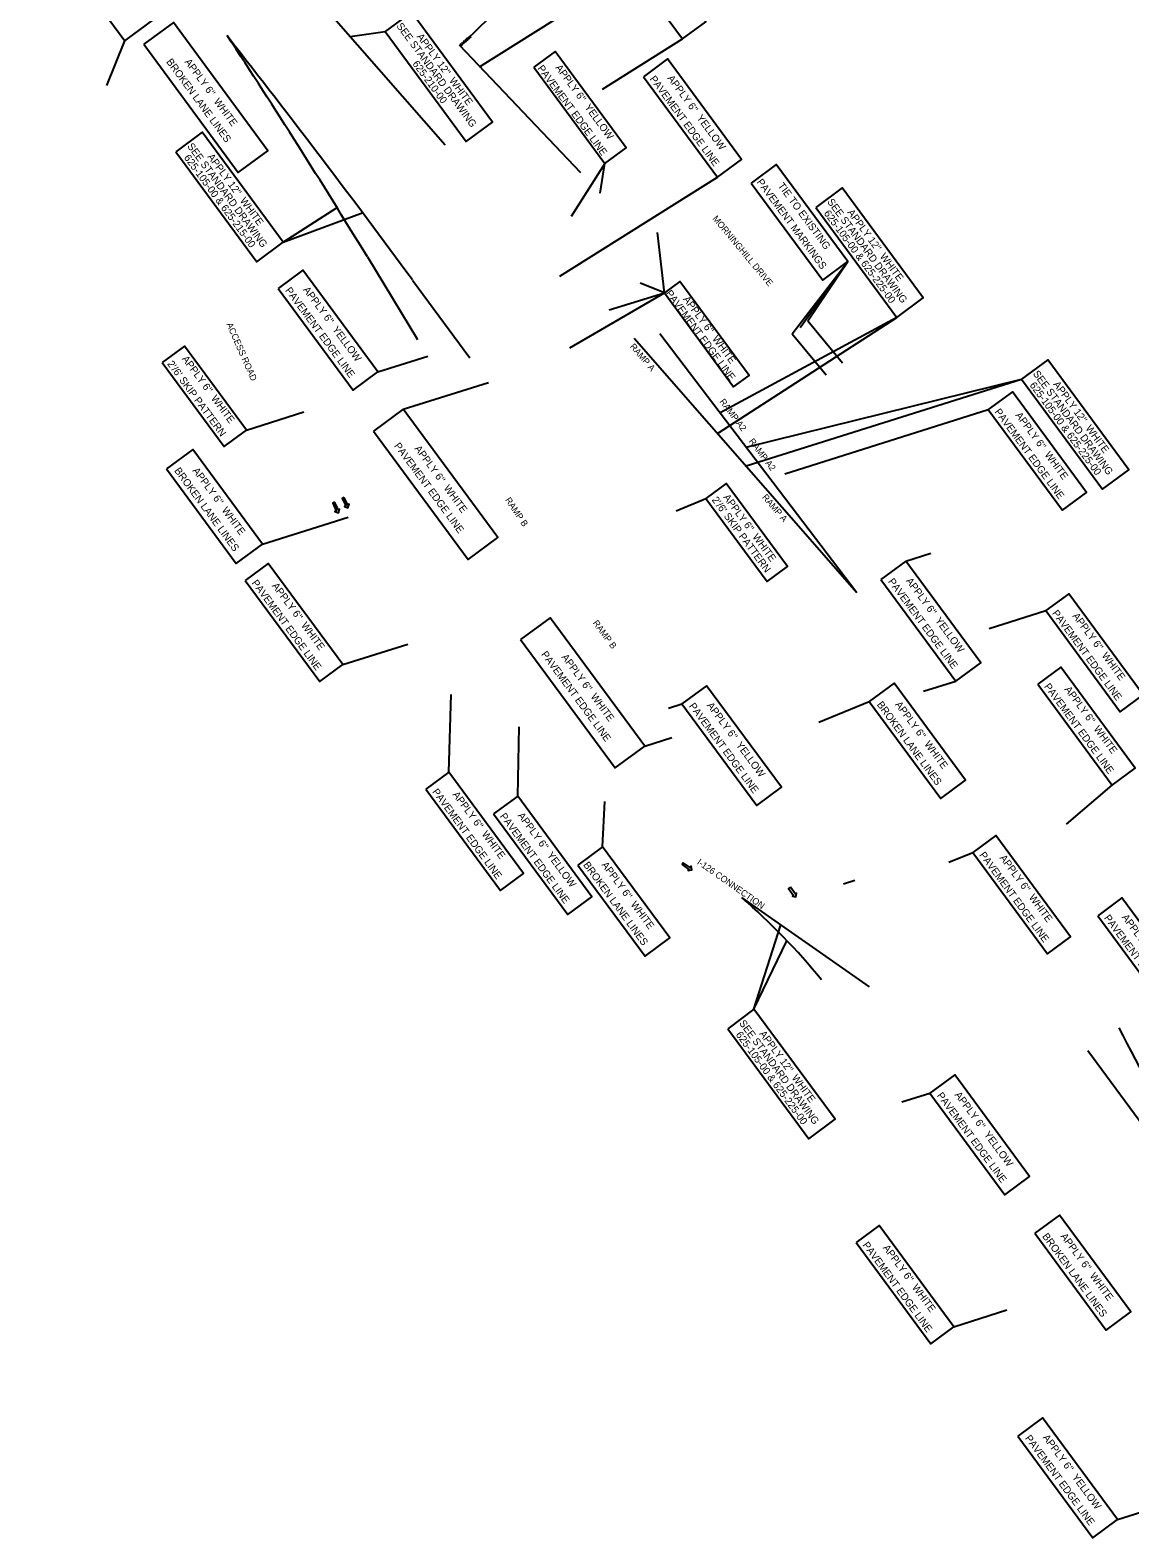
# Model space of a CAD drawing. Extents: x 1966013 to 1974896, y 789499 to 804826.
# Drawn here: x 1970033 to 1971229, y 795539 to 797178 of the extents above; entities that cross this region are included whole.
import ezdxf

# ---------------------------------------------------------------- set-up
doc = ezdxf.new("R2010")
doc.units = 0
for name, color, linetype in [('RD_EX_H2O_BlueLn', 7, 'Continuous'), ('RD_PD_Final_Cl', 7, 'Continuous'), ('RD_PD_Final_LnLine', 7, 'Continuous'), ('RD_PD_MedBWall', 7, 'Continuous')]:
    doc.layers.add(name, color=color, linetype=linetype)

msp = doc.modelspace()

# ---------------------------------------------------------------- linework, layer by layer
at = {"layer": 'RD_EX_H2O_BlueLn'}
for p, q in [((1970507, 797167), (1970581.9, 797240.7)), ((1970521.6, 797138.2), (1970648.7, 797217.9)), ((1970380.7, 797171.2), (1970418.8, 797176.4)), ((1970116.1, 797117.8), (1970135.6, 797166.3)), ((1970500.4, 797162.4), (1970501.6, 797163.3)), ((1970502.4, 797161.1), (1970500.4, 797162.4)), ((1970501.6, 797163.3), (1970502.4, 797161.1)), ((1970502.3, 797164), (1970503.5, 797165)), ((1970504.3, 797162.8), (1970502.3, 797164)), ((1970503.5, 797165), (1970504.3, 797162.8)), ((1970504.2, 797165.6), (1970505.3, 797166.6)), ((1970506.2, 797164.4), (1970504.2, 797165.6)), ((1970505.3, 797166.6), (1970506.2, 797164.4)), ((1970506.1, 797167.3), (1970507.3, 797168.3)), ((1970508.1, 797166.1), (1970506.1, 797167.3)), ((1970507.3, 797168.3), (1970508.1, 797166.1)), ((1970507.9, 797168.9), (1970509, 797169.9)), ((1970509.9, 797167.7), (1970507.9, 797168.9)), ((1970509, 797169.9), (1970509.9, 797167.7)), ((1970509.8, 797170.5), (1970510.9, 797171.5)), ((1970511.8, 797169.3), (1970509.8, 797170.5)), ((1970510.9, 797171.5), (1970511.8, 797169.3)), ((1970655.2, 797113.8), (1970742.3, 797168.4)), ((1970657.8, 797032.9), (1970621.2, 796975.5)), ((1970652.7, 797000.8), (1970657.8, 797032.9)), ((1970609.1, 796910.5), (1970780.4, 797018)), ((1970308, 796947.3), (1970366.6, 796985)), ((1970308, 796947.3), (1970395.1, 796979.6)), ((1970722.6, 796892.2), (1970715.2, 796957.9)), ((1970861.7, 796847.8), (1970922.3, 796926.5)), ((1970870.2, 796854.8), (1970922.3, 796926.5)), ((1970878.6, 796861.8), (1970922.3, 796926.5)), ((1970722.6, 796892.2), (1970696.3, 796902.9)), ((1970619.9, 796832.5), (1970722.6, 796892.2)), ((1970662.6, 796873.8), (1970722.6, 796892.2)), ((1970780.3, 796739.3), (1970975.5, 796865.7)), ((1970975.5, 796865.7), (1970783.2, 796762)), ((1970878.6, 796861.8), (1970916.3, 796816.2)), ((1970861.7, 796847.8), (1970898.6, 796803.1)), ((1970410.9, 796806.5), (1970465.4, 796823.6)), ((1970811.5, 796704.1), (1971111.1, 796798.4)), ((1970811.6, 796724.7), (1971111.1, 796798.4)), ((1970438.6, 796765.8), (1970531.2, 796795)), ((1970853.7, 796695.7), (1971075, 796765.4)), ((1970268, 796743.2), (1970330.6, 796762.9)), ((1970735.4, 796655.5), (1970767.9, 796668.8)), ((1970285.5, 796619.1), (1970378.8, 796648.5)), ((1970985.2, 796600.6), (1971012.5, 796609.2)), ((1971075.9, 796527.4), (1971137.4, 796546.8)), ((1970373, 796488.1), (1970443.7, 796510.4)), ((1971004.5, 796459.1), (1971039.7, 796470.2)), ((1970488.2, 796371.1), (1970490.7, 796455.5)), ((1970727.1, 796440.8), (1970741.7, 796445.3)), ((1970890.5, 796425.4), (1970945.5, 796447.9)), ((1970563.2, 796345), (1970564.8, 796420.5)), ((1970701.4, 796399.6), (1970730.9, 796408.9)), ((1971159.9, 796314.7), (1971209.8, 796357)), ((1970655.5, 796290.1), (1970657.7, 796339.4)), ((1971032.2, 796273.2), (1971058.3, 796283.8)), ((1970917.3, 796249.8), (1970929.8, 796253.7)), ((1970820.1, 796113.3), (1970849.3, 796205)), ((1970820.1, 796113.3), (1970855.9, 796187.7)), ((1970981.1, 796012.7), (1971011.5, 796022.2)), ((1971037.5, 795768.2), (1971095.3, 795786.4)), ((1971215.6, 795558.5), (1971320.9, 795591.6))]:
    msp.add_line(p, q, dxfattribs=at)
for points in [[(1970032.8, 797305.8), (1970135.6, 797166.3), (1970167.8, 797190), (1970065, 797329.5)], [(1970662.7, 797276.4), (1970742.3, 797168.4), (1970767.6, 797187.1), (1970688.1, 797295.1)], [(1970418.8, 797176.4), (1970506.9, 797056.8), (1970535.6, 797077.9), (1970447.4, 797197.5)], [(1970156.4, 797162.6), (1970259.2, 797023.1), (1970291.4, 797046.8), (1970188.6, 797186.4)], [(1970580.5, 797137.7), (1970657.8, 797032.9), (1970681, 797050), (1970603.8, 797154.8)], [(1970699.8, 797127.4), (1970780.4, 797018), (1970806.7, 797037.3), (1970726, 797146.7)], [(1970191.2, 797045.8), (1970279.4, 796926.2), (1970308, 796947.3), (1970219.8, 797066.9)], [(1970817, 797011.7), (1970895.1, 796906.3), (1970922.3, 796926.5), (1970844.2, 797031.9)], [(1970887.3, 796985.3), (1970975.5, 796865.7), (1971004.1, 796886.8), (1970916, 797006.4)], [(1970302.5, 796897.2), (1970384, 796786.6), (1970410.9, 796806.5), (1970329.4, 796917.1)], [(1970722.6, 796892.2), (1970797.9, 796790.1), (1970814.8, 796802.6), (1970739.6, 796904.7)], [(1970176.5, 796816.5), (1970243.7, 796725.3), (1970268, 796743.2), (1970200.8, 796834.4)], [(1971111.1, 796798.4), (1971199.3, 796678.8), (1971227.9, 796699.9), (1971139.7, 796819.5)], [(1971075, 796765.4), (1971155.6, 796656), (1971181.9, 796675.3), (1971101.2, 796784.7)], [(1970406.4, 796742.1), (1970509.3, 796602.5), (1970541.5, 796626.3), (1970438.6, 796765.8)], [(1970181.1, 796700.9), (1970256.9, 796598), (1970285.5, 796619.1), (1970209.7, 796721.9)], [(1970767.9, 796668.8), (1970834.4, 796578.5), (1970856.5, 796594.7), (1970789.9, 796685)], [(1970958.2, 796580.7), (1971039.7, 796470.2), (1971066.7, 796490), (1970985.2, 796600.6)], [(1970266.8, 796579.6), (1970347.9, 796469.6), (1970373, 796488.1), (1970291.8, 796598.1)], [(1971137.4, 796546.8), (1971218.5, 796436.7), (1971243.6, 796455.2), (1971162.5, 796565.2)], [(1970566.3, 796515.4), (1970669.2, 796375.9), (1970701.4, 796399.6), (1970598.5, 796539.1)], [(1971128.7, 796467), (1971209.8, 796357), (1971234.9, 796375.5), (1971153.8, 796485.5)], [(1970741.7, 796445.3), (1970823.2, 796334.8), (1970850.1, 796354.7), (1970768.6, 796465.2)], [(1970945.5, 796447.9), (1971023.2, 796342.6), (1971050.1, 796362.5), (1970972.5, 796467.8)], [(1970463.2, 796352.6), (1970544.3, 796242.5), (1970569.3, 796261), (1970488.2, 796371.1)], [(1970536.9, 796325.7), (1970617.6, 796216.3), (1970643.8, 796235.6), (1970563.2, 796345)], [(1970628.6, 796270.2), (1970701.7, 796171.1), (1970728.6, 796190.9), (1970655.5, 796290.1)], [(1971058.3, 796283.8), (1971139.4, 796173.8), (1971164.5, 796192.3), (1971083.3, 796302.3)], [(1971194.1, 796215.1), (1971274.7, 796105.7), (1971301, 796125), (1971220.3, 796234.4)], [(1970791.5, 796092.2), (1970879.7, 795972.6), (1970908.3, 795993.7), (1970820.1, 796113.3)], [(1971011.5, 796022.2), (1971093.1, 795911.6), (1971119.9, 795931.4), (1971038.4, 796042.1)], [(1970931.3, 795859.8), (1971012.4, 795749.7), (1971037.5, 795768.2), (1970956.3, 795878.2)], [(1971125.5, 795869.8), (1971203.1, 795764.5), (1971230, 795784.3), (1971152.4, 795889.6)], [(1971107.1, 795649.2), (1971188.6, 795538.6), (1971215.6, 795558.5), (1971134.1, 795669)]]:
    msp.add_lwpolyline(points, close=True, dxfattribs=at)
at = {"layer": 'RD_PD_Final_Cl'}
for points in [[(1970374.5, 796670), (1970372.3, 796668.9), (1970376.2, 796660.6), (1970374.7, 796659.9), (1970378.5, 796658.6), (1970379.9, 796662.4), (1970378.4, 796661.7)], [(1970364, 796664.7), (1970361.9, 796663.6), (1970365.8, 796655.3), (1970364.3, 796654.7), (1970368.1, 796653.3), (1970369.4, 796657.1), (1970368, 796656.4)], [(1970743.2, 796272.7), (1970741.9, 796270.7), (1970749.4, 796265.5), (1970748.4, 796264.2), (1970752.4, 796264.8), (1970751.7, 796268.8), (1970750.8, 796267.5)], [(1970859.7, 796246), (1970857.7, 796244.6), (1970863.2, 796237.2), (1970861.9, 796236.3), (1970865.8, 796235.7), (1970866.4, 796239.6), (1970865.1, 796238.6)]]:
    msp.add_lwpolyline(points, close=True, dxfattribs=at)
at = {"layer": 'RD_PD_Final_LnLine'}
for p, q in [((1970331.9, 797227), (1970484.2, 797053.2)), ((1970499.5, 797162.1), (1970631.3, 797023.2)), ((1970399.6, 796931.4), (1970454.2, 796841.8)), ((1970448.7, 796906.3), (1970511.1, 796821.7)), ((1970717.8, 796848.1), (1970931.8, 796566.4)), ((1970689.6, 796843), (1970931.8, 796566.4)), ((1970945.7, 796137.6), (1970806.8, 796234.9)), ((1971183.3, 796068.4), (1971259.3, 795965.3))]:
    msp.add_line(p, q, dxfattribs=at)
for centre, radius, start, end in [((1963181.8, 792526), 8456, 31.39766, 33.32963), ((1961201.8, 790089.5), 11488, 36.39766, 38.04902), ((1970326.5, 795682.5), 732, 39.2393, 48.9944), ((1972855.7, 796921.2), 1836, 206.8053, 216.4039)]:
    msp.add_arc(centre, radius, start, end, dxfattribs=at)

# ---------------------------------------------------------------- texts
at = {"layer": 'RD_EX_H2O_BlueLn'}
for s, height, rotation, p in [('SEE STANDARD DRAWING', 8, 306.3977, (1970430.8, 797182.4)), ("APPLY 12''  WHITE", 8, 306.3977, (1970452.8, 797170.8)), ('BROKEN LANE LINES', 8, 306.3977, (1970180.4, 797143.5)), ("APPLY 6''  WHITE", 8, 306.3977, (1970200.3, 797143.4)), ('625-210-00 ', 8, 306.3977, (1970448.2, 797141.3)), ('PAVEMENT EDGE LINE', 8, 306.3977, (1970584.2, 797136.4)), ("APPLY 6''  YELLOW", 8, 306.3977, (1970603.6, 797137.1)), ('PAVEMENT EDGE LINE', 8, 306.3977, (1970706.2, 797124.9)), ("APPLY 6''  YELLOW", 8, 306.3977, (1970725.5, 797125.6)), ('625-105-00 & 625-215-00', 8, 306.3977, (1970199.6, 797039.2)), ('SEE STANDARD DRAWING', 8, 306.3977, (1970203.2, 797051.7)), ("APPLY 12''  WHITE", 8, 306.3977, (1970225.2, 797040.2)), ('PAVEMENT MARKINGS', 8, 306.5163, (1970822.7, 797012.7)), ('TIE TO EXISTING', 8, 306.5163, (1970845.6, 797008.7)), ('SEE STANDARD DRAWING', 8, 306.3977, (1970899.3, 796991.3)), ('625-105-00 & 625-225-00', 8, 306.3977, (1970895.7, 796978.7)), ("APPLY 12''  WHITE", 8, 306.3977, (1970921.3, 796979.7)), ('PAVEMENT EDGE LINE', 8, 306.3977, (1970309.8, 796894.9)), ("APPLY 6''  YELLOW", 8, 306.3977, (1970329.2, 796895.6)), ('PAVEMENT EDGE LINE', 8, 306.3977, (1970723.6, 796891.8)), ("APPLY 6''  WHITE", 8, 306.3977, (1970742.5, 796885.3)), ("2'/6' SKIP PATTERN", 7.999, 306.3978, (1970181.4, 796815.1)), ("APPLY 6''  WHITE", 7.999, 306.3978, (1970197.4, 796820.5)), ('SEE STANDARD DRAWING', 8, 306.3977, (1971123.1, 796804.4)), ('625-105-00 & 625-225-00', 8, 306.3977, (1971119.5, 796791.8)), ("APPLY 12''  WHITE", 8, 306.3977, (1971145.1, 796792.8)), ('PAVEMENT EDGE LINE', 8, 306.3977, (1971081.4, 796762.9)), ("APPLY 6''  WHITE", 8, 306.3977, (1971104, 796759.2)), ('PAVEMENT EDGE LINE', 8, 306.3977, (1970428.3, 796725.9)), ("APPLY 6''  WHITE", 8, 306.3977, (1970450.4, 796722.9)), ('BROKEN LANE LINES', 8, 306.3977, (1970189.1, 796698.9)), ("APPLY 6''  WHITE", 8, 306.3977, (1970209, 796698.9)), ("2'/6' SKIP PATTERN", 7.999, 306.3978, (1970773.8, 796667.2)), ("APPLY 6''  WHITE", 7.999, 306.3978, (1970786.3, 796670)), ('PAVEMENT EDGE LINE', 8, 306.3977, (1970273.3, 796576.8)), ("APPLY 6''  WHITE", 8, 306.3977, (1970295.4, 796573.7)), ('PAVEMENT EDGE LINE', 8, 306.3977, (1970965.6, 796578.4)), ("APPLY 6''  YELLOW", 8, 306.3977, (1970984.9, 796579.1)), ('PAVEMENT EDGE LINE', 8, 306.3977, (1971144, 796543.9)), ("APPLY 6''  WHITE", 8, 306.3977, (1971166.1, 796540.9)), ('PAVEMENT EDGE LINE', 8, 306.3977, (1970588.2, 796499.2)), ("APPLY 6''  WHITE", 8, 306.3977, (1970610.3, 796496.2)), ('PAVEMENT EDGE LINE', 8, 306.3977, (1971135.3, 796464.2)), ("APPLY 6''  WHITE", 8, 306.3977, (1971157.4, 796461.1)), ('PAVEMENT EDGE LINE', 8, 306.3977, (1970749, 796443)), ("APPLY 6''  YELLOW", 8, 306.3977, (1970768.4, 796443.7)), ('BROKEN LANE LINES', 8, 306.3977, (1970953.3, 796444.6)), ("APPLY 6''  WHITE", 8, 306.3977, (1970973.2, 796444.6)), ('PAVEMENT EDGE LINE', 8, 306.3977, (1970469.7, 796349.7)), ("APPLY 6''  WHITE", 8, 306.3977, (1970491.8, 796346.7)), ('PAVEMENT EDGE LINE', 8, 306.3977, (1970543.3, 796323.2)), ("APPLY 6''  YELLOW", 8, 306.3977, (1970562.7, 796323.9)), ('BROKEN LANE LINES', 8, 306.3977, (1970633.9, 796270.3)), ("APPLY 6''  WHITE", 8, 306.3977, (1970653.8, 796270.3)), ('PAVEMENT EDGE LINE', 8, 306.3977, (1971064.8, 796281)), ("APPLY 6''  WHITE", 8, 306.3977, (1971086.9, 796277.9)), ('PAVEMENT EDGE LINE', 8, 306.3977, (1971200.5, 796212.6)), ("APPLY 6''  YELLOW", 8, 306.3977, (1971219.8, 796213.3)), ('SEE STANDARD DRAWING', 8, 306.3977, (1970803.5, 796098.2)), ('625-105-00 & 625-225-00', 8, 306.3977, (1970799.9, 796085.6)), ("APPLY 12''  WHITE", 8, 306.3977, (1970825.5, 796086.6)), ('PAVEMENT EDGE LINE', 8, 306.3977, (1971018.7, 796019.5)), ("APPLY 6''  YELLOW", 8, 306.3977, (1971038, 796020.2)), ('BROKEN LANE LINES', 8, 306.3977, (1971133.2, 795866.4)), ("APPLY 6''  WHITE", 8, 306.3977, (1971153.1, 795866.4)), ('PAVEMENT EDGE LINE', 8, 306.3977, (1970937.8, 795856.9)), ("APPLY 6''  WHITE", 8, 306.3977, (1970959.9, 795853.9)), ('PAVEMENT EDGE LINE', 8, 306.3977, (1971114.5, 795646.9)), ("APPLY 6''  YELLOW", 8, 306.3977, (1971133.8, 795647.6))]:
    msp.add_text(s, height=height, rotation=rotation, dxfattribs=at).set_placement(p)
at = {"layer": 'RD_PD_Final_Cl'}
msp.add_text('I-126 CONNECTION', height=7, rotation=324.9411, dxfattribs=at).set_placement((1970757.5, 796271.8))
at = {"layer": 'RD_PD_MedBWall'}
for s, rotation, p in [('MORNINGHILL DRIVE', 309.8296, (1970774.5, 796972.8)), ('ACCESS ROAD', 293.6466, (1970246.1, 796858.2)), ('RAMP A', 310.7291, (1970684.7, 796833.6)), ('RAMP A2', 306.9333, (1970782.3, 796774)), ('RAMP A2', 306.9333, (1970814.1, 796730.9)), ('RAMP B', 303.9445, (1970549.1, 796667.1)), ('RAMP A', 310.7291, (1970828.5, 796669.8)), ('RAMP B', 306.4679, (1970644.4, 796533.3))]:
    msp.add_text(s, height=7, rotation=rotation, dxfattribs=at).set_placement(p)

doc.saveas('drawing.dxf')
